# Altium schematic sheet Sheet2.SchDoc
size B; SheetNumber: 1; SheetTotal: 1
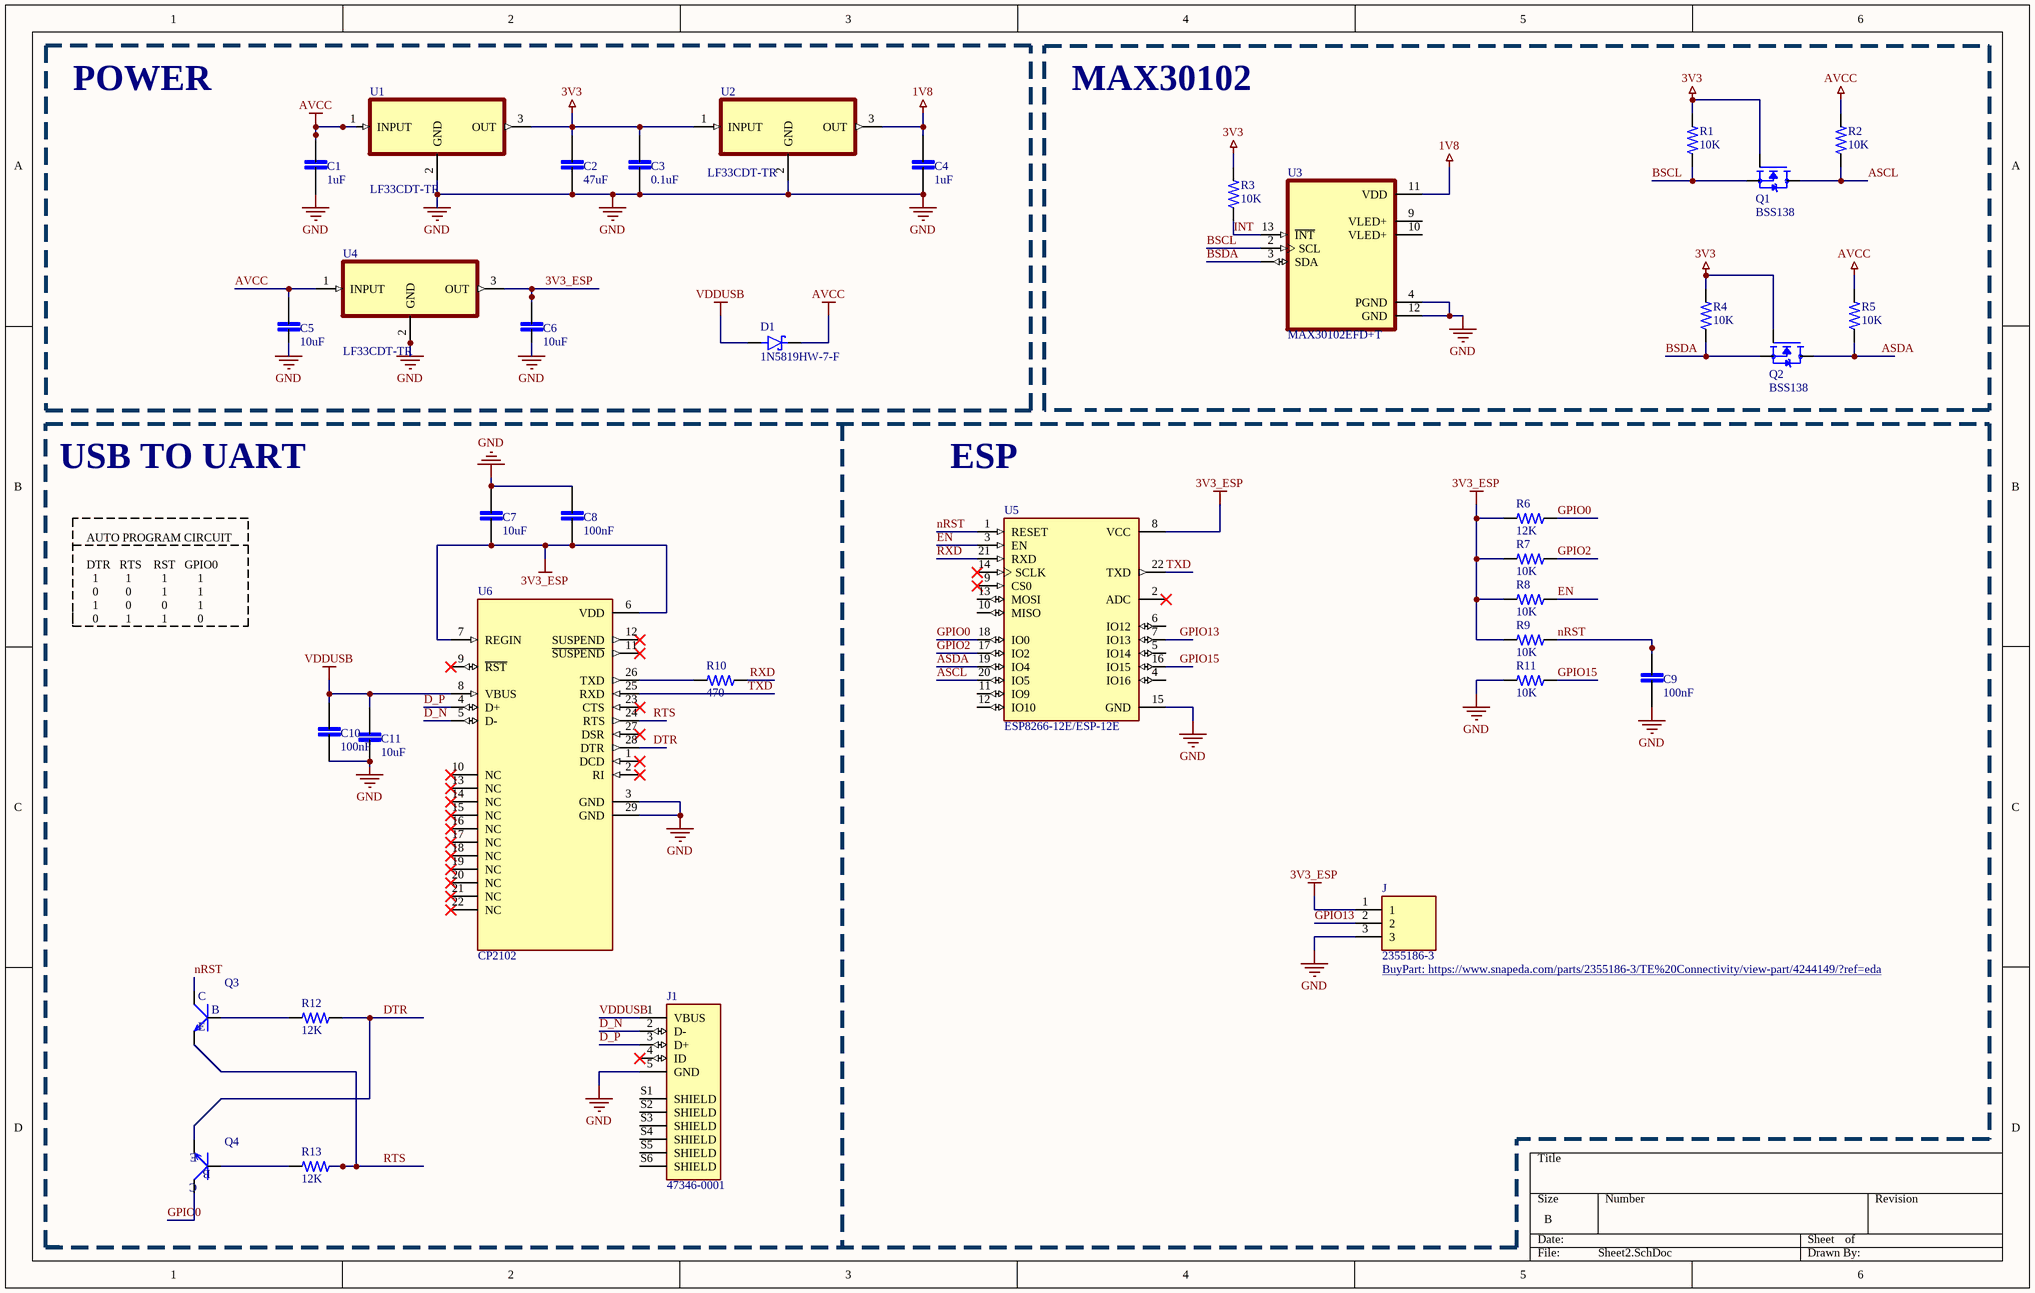
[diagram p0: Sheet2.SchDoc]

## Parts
C1  1uF  [CAPC2012X140N]
C2  47uF  [CAPC2012X140N]
C3  0.1uF  [CAPC2012X140N]
C4  1uF  [CAPC2012X140N]
C5  10uF  [CAPC2012X140N]
C6  10uF  [CAPC2012X140N]
C7  10uF  [CAPC2012X140N]
C8  100nF  [CAPC2012X140N]
C9  100nF  [CAPC2012X140N]
C10  100nF  [CAPC2012X140N]
C11  10uF  [CAPC2012X140N]
D1  1N5819HW-7-F  [SOD3715X145N]
J  2355186-3  [TE_2355186-3]
J1  47346-0001  [MOLEX_47346-0001]
Q1  BSS138  [SOT95P240X111-3N]
Q2  BSS138  [SOT95P240X111-3N]
Q3  SMD-TRANSISTORS-NPN-25V-500MW(SOT-23)  [SOT-23]  (value not drawn)
Q4  SMD-TRANSISTORS-NPN-25V-500MW(SOT-23)  [SOT-23]  (value not drawn)
R1  10K  [RESC2012X65N]
R2  10K  [RESC2012X65N]
R3  10K  [RESC2012X65N]
R4  10K  [RESC2012X65N]
R5  10K  [RESC2012X65N]
R6  12K  [RESC2012X65N]
R7  10K  [RESC2012X65N]
R8  10K  [RESC2012X65N]
R9  10K  [RESC2012X65N]
R10  470  [RESC2012X65N]
R11  10K  [RESC2012X65N]
R12  12K  [RESC2012X65N]
R13  12K  [RESC2012X65N]
U1  LF33CDT-TR  [TO228P972X240-3N]
U2  LF33CDT-TR  [TO228P972X240-3N]
U3  MAX30102EFD+T  [XDCR_MAX30101EFD+]
U4  LF33CDT-TR  [TO228P972X240-3N]
U5  ESP8266-12E/ESP-12E  [XCVR_ESP8266-12E/ESP-12E]
U6  CP2102  [QFN50P500X500X100-29N]

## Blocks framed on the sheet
POWER: C1-C6 D1 U1 U2 U4

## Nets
1V8: C4.2 U2.3(OUT) U3.11(VDD)
3V3: C2.2 C3.2 Q1.1(G) Q2.1(G) R1.2 R3.2 R4.2 U1.3(OUT) U2.1(INPUT)
3V3_ESP: C6.2 C7.1 C8.1 J.1 R6.2 R7.2 R8.2 R9.2 U4.3(OUT) U5.8(VCC) U6.6(VDD) U6.7(REGIN)
AVCC: C1.2 C5.2 D1.C(K) R2.2 R5.2 U1.1(INPUT) U4.1(INPUT)
GND: C1.1 C2.1 C3.1 C4.1 C5.1 C6.1 C7.2 C8.2 C9.1 C10.1 C11.1 J.3 J1.5(GND) R11.2 U1.2(GND) U2.2(GND) U3.4(PGND) U3.12(GND) U4.2(GND) U5.15(GND) U6.3(GND) U6.29(GND)
VDDUSB: C10.2 C11.2 D1.A J1.1(VBUS) U6.8(VBUS)
ASCL: Q1.3(D) R2.1 U5.20(IO5)
ASDA: Q2.3(D) R5.1 U5.19(IO4)
BSCL: Q1.2(S) R1.1 U3.2(SCL)
BSDA: Q2.2(S) R4.1 U3.3(SDA)
D_N: J1.2(D-) U6.5(D-)
D_P: J1.3(D+) U6.4(D+)
DTR: Q4.2(E) R12.1 U6.28(DTR)
EN: R8.1 U5.3(EN)
GPIO0: Q4.3(C) R6.1 U5.18(IO0)
GPIO2: R7.1 U5.17(IO2)
GPIO13: J.2 U5.7(IO13)
GPIO15: R11.1 U5.16(IO15)
INT: R3.1 U3.13(~{INT})
nRST: C9.2 Q3.3(C) R9.1 U5.1(RESET)
RTS: Q3.2(E) R13.1 U6.24(RTS)
RXD: R10.1 U5.21(RXD)
TXD: U5.22(TXD) U6.25(RXD)
NetQ3_1: Q3.1(B) R12.2
NetQ4_1: Q4.1(B) R13.2
NetR10_2: R10.2 U6.26(TXD)

Not connected (* = marked no-connect by the designer): J1 4(ID)* S1(SHIELD) S2(SHIELD) S3(SHIELD) S4(SHIELD) S5(SHIELD) S6(SHIELD); U3 9(VLED+) 10(VLED+); U5 2(ADC)* 4(IO16) 5(IO14) 6(IO12) 9(CS0)* 10(MISO) 11(IO9) 12(IO10) 13(MOSI) 14(SCLK)*; U6 1(DCD)* 2(RI)* 9(~{RST})* 10(NC)* 11(~{SUSPEND})* 12(SUSPEND)* 13(NC)* 14(NC)* 15(NC)* 16(NC)* 17(NC)* 18(NC)* 19(NC)* 20(NC)* 21(NC)* 22(NC)* 23(CTS)* 27(DSR)*

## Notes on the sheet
- MAX30102
- USB TO UART
- ESP
- AUTO PROGRAM CIRCUIT
  DTR   RTS    RST   GPIO0
  1         1          1          1
  0         0          1          1
  1         0          0          1
  0         1          1          0

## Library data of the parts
C1-C11 = LD051C121KAB2A: Ceramic Capacitor; MF: AVX
D1 = 1N5819HW-7-F: Diode Schottky 40 V 1A Surface Mount SOD-123; MF: Diodes Inc.
J = 2355186-3: Pin 3P,2MM,BRK HDR,SRVT,2.8,0.76AU,BOX 3 POS; MF: TE Connectivity
J1 = 47346-0001: USB - micro B USB 2.0 Receptacle Connector 5 Position Surface Mount, Right Angle; MF: Molex
Q1 Q2 = BSS138: N-Channel 50 V 220mA (Ta) 350mW (Ta) Surface Mount SOT-23-3; MF: onsemi
Q3 Q4 = SMD-TRANSISTORS-NPN-25V-500MW(SOT-23): Bipolar (BJT) Transistor NPN 25 V 500 mA 150MHz 300 mW Surface Mount SOT-23; MF: UMW; MP: S8050
R1-R13 = 2-2176053-0: RES 0.33 OHM 1% 1/4W 0805; Power_Rating: .25 W; Resistance: .33; MF: TE Connectivity
U1 U2 U4 = LF33CDT-TR: Linear Voltage Regulator IC Positive Fixed 1 Output 500mA DPAK; MF: STMicroelectronics
U3 = MAX30102EFD+T: Pulse Oximeter and Heart Rate Sensor Digital Output; MF: Maxim Integrated Products
U5 = ESP8266-12E/ESP-12E: This WiFi module has a 32-bit MCU micro and clock speeds supporting 80 MHz or 160 MHz. Supports the RTOS and integrated Wi-Fi MAC/BB/RF/PA/LNA, and has an on-board antenna.; MF: AI-Thinker
U6 = CP2102: CP2102N USB 2.0 to UART (RS232) Bridge Interface Evaluation Board; MF: Silicon Labs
